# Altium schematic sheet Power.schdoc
size 282 x 196 mm
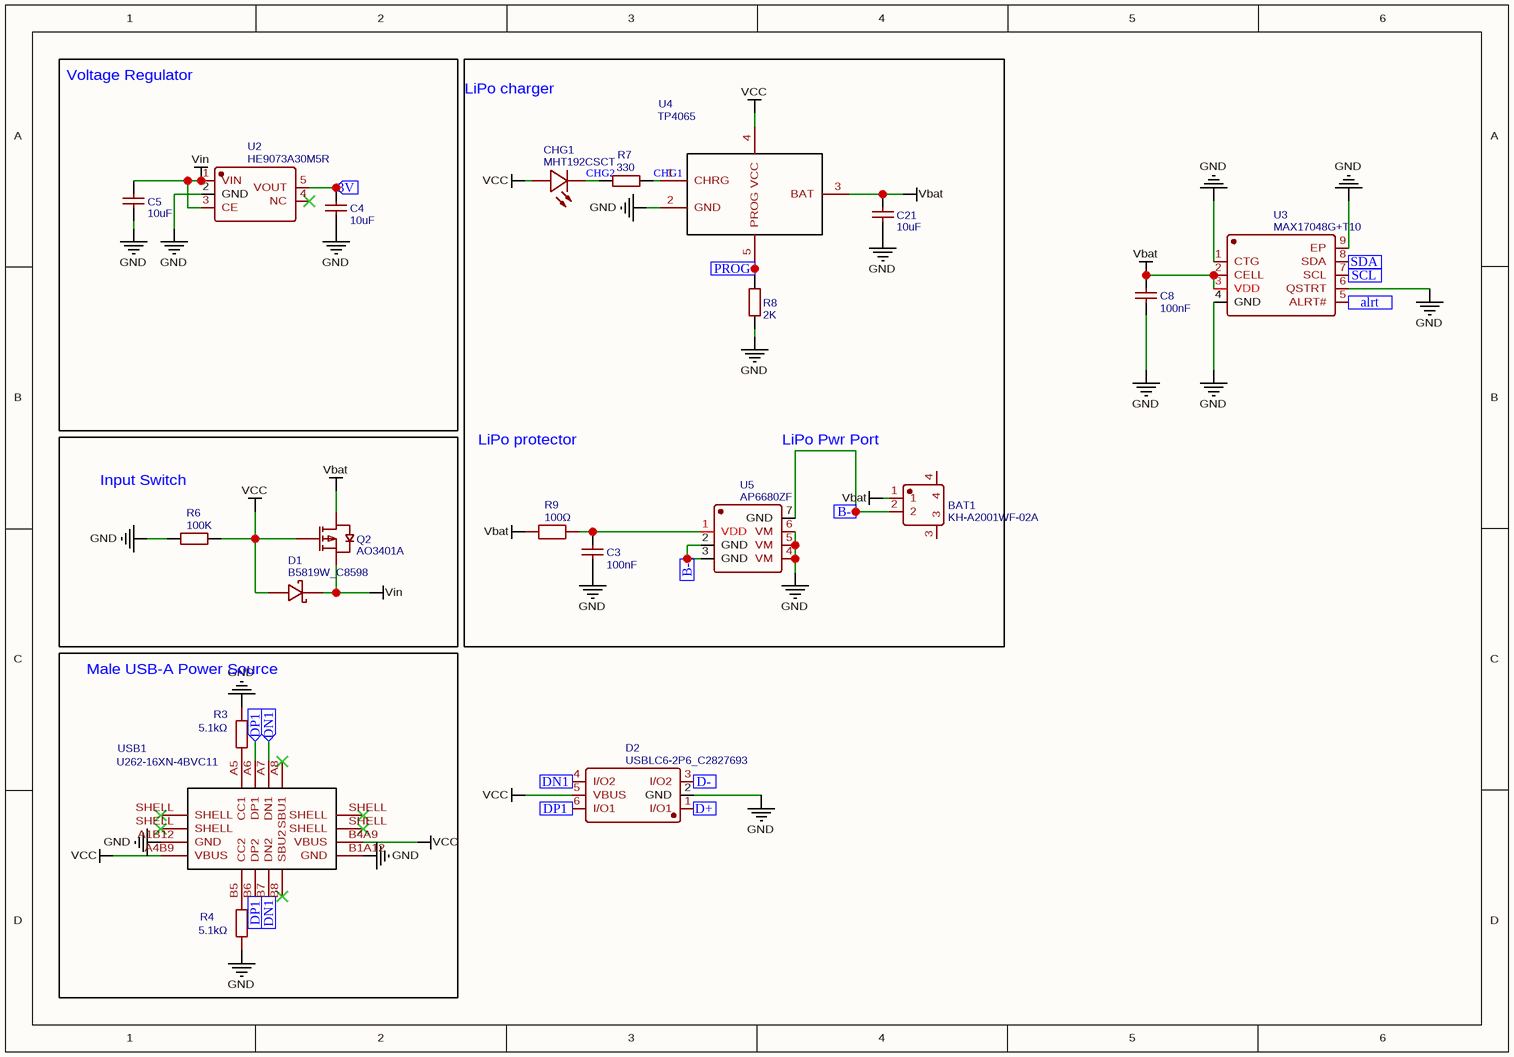
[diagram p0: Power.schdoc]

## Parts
BAT1  KH-A2001WF-02A  [CONN-SMD_KH-A2001WF-02A]
C3  100nF  [C0402]
C4  10uF  [C0402]
C5  10uF  [C0402]
C8  100nF  [C0402]
C21  10uF  [C0402]
CHG1  MHT192CSCT  [LED0603-R-RD_ORANGE]
D1  B5819W_C8598  [SOD-123_L2.7-W1.6-LS3.7-RD-1]
D2  USBLC6-2P6_C2827693  [SOT-666-6_L1.6-W1.2-P0.50-LS1.6-BL]
Q2  AO3401A  [SOT-23_L2.9-W1.3-P0.95-LS2.4-BR]
R3  5.1kΩ  [R0402]
R4  5.1kΩ  [R0402]
R6  100K  [R0402]
R7  330  [R0402]
R8  2K  [R0402]
R9  100Ω  [R0402]
U2  HE9073A30M5R  [SOT-23-5_L3.0-W1.7-P0.95-LS2.8-BL]
U3  MAX17048G+T10  [DFN-8_L2.0-W2.0-P0.50-BL-EP]
U4  TP4065  [SOT-23-5_L3.0-W1.7-P0.95-LS2.8-BR]
U5  AP6680ZF  [DFN-6_L2.0-W2.0-P0.65-BL-EP1.2]
USB1  U262-16XN-4BVC11  [USB-3.1-SMD_U262-161N-4BVC11]

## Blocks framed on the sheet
Voltage Regulator: C4 C5 U2
Input Switch: D1 Q2 R6
Male USB-A Power Source: R3 R4 USB1

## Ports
3V (in), alrt (in), B- (in), D+ (in), D- (in), DN1 (in), DP1 (in), PROG (in), SCL (in), SDA (in)

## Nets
GND: C3.1 C4.1 C5.1 C8.1 C21.1 D2.2(GND) R3.2 R4.1 R6.1 R8.1 U2.2(GND) U3.1(CTG) U3.4(GND) U3.6(QSTRT) U3.9(EP) U4.2(GND) U5.4(VM) U5.5(VM) U5.6(VM) USB1.A1B12(GND) USB1.B1A12(GND)
Vbat: BAT1.1 C8.2 C21.2 Q2.3(D) R9.1 U3.2(CELL) U3.3(VDD) U4.3(BAT)
VCC: CHG1.1(A) D1.2(+) D2.5(VBUS) Q2.1(G) R6.2 U4.4(VCC) USB1.A4B9(VBUS) USB1.B4A9(VBUS)
Vin: C5.2 D1.1(-) Q2.2(S) U2.1(VIN) U2.3(CE)
3V: C4.2 U2.5(VOUT) ; port 3V
alrt: U3.5(ALRT#) ; port alrt
B-: BAT1.2 U5.2(GND) U5.3(GND) U5.7(GND) ; port B-
CHG1: R7.2 U4.1(CHRG)
CHG2: CHG1.2(K) R7.1
D+: D2.1(I/O1) ; port D+
D-: D2.3(I/O2) ; port D-
DN1: D2.4(I/O2) USB1.A7(DN1) USB1.B7(DN2) ; port DN1
DP1: D2.6(I/O1) USB1.A6(DP1) USB1.B6(DP2) ; port DP1
PROG: R8.2 U4.5(PROG) ; port PROG
SCL: U3.7(SCL) ; port SCL
SDA: U3.8(SDA) ; port SDA
NetC3_2: C3.2 R9.2 U5.1(VDD)
NetR3_1: R3.1 USB1.A5(CC1)
NetR4_2: R4.2 USB1.B5(CC2)

Not connected (* = marked no-connect by the designer): BAT1 3 4; U2 4(NC)*; USB1 A8(SBU1)* B8(SBU2)* SHELL*

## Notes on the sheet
- LiPo charger
- LiPo protector
- LiPo Pwr Port

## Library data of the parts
BAT1 = KH-A2001WF-02A: Manufacturer: kinghelm(金航标); Contributor: LCSC
C3 C8 = 100nF: Manufacturer: FH(风华); Manufacturer Part: 0402B104K160NT; nameAlias: Capacitance
C4 C5 C21 = 10uF: Manufacturer Part: CL05A106MQ5NUNC; Manufacturer: SAMSUNG; nameAlias: Capacitance; SMT Type: Basic
CHG1 = MHT192CSCT: Manufacturer: MEIHUA(美华); Contributor: LCSC
D1 = B5819W_C8598: Manufacturer: CJ; Manufacturer Part: B5819W
D2 = USBLC6-2P6_C2827693: Manufacturer: TECH PUBLIC(台舟); Contributor: LCSC
Q2 = AO3401A: Manufacturer: AOS; SMT Type: Basic
R3 R4 = 5.1kΩ: Manufacturer: 大毅科技; Manufacturer Part: RM04FTN5101; Resistance (Ohms): 5.1K; nameAlias: Resistance; Contributor: LCSC
R6 = 100K: Manufacturer: UniOhm; Manufacturer Part: 0402WGF1003TCE; nameAlias: Resistance (Ohms)
R7 = 330: Manufacturer: UniOhm; Manufacturer Part: 0402WGF3300TCE; nameAlias: Resistance (Ohms)
R8 = 2K: Manufacturer Part: 0402WGF2001TCE; Manufacturer: UniOhm; nameAlias: Resistance (Ohms)
R9 = 100Ω: Manufacturer: VO(翔胜); Manufacturer Part: SCR0402J100R; Contributor: lcsc; nameAlias: Value
U2 = HE9073A30M5R: Manufacturer: HEERMICR(赫尔半导体); Contributor: LCSC
U3 = MAX17048G+T10: Manufacturer: ADI(亚德诺); Contributor: LCSC
U4 = TP4065: Manufacturer: TOPPOWER
U5 = AP6680ZF: Manufacturer: ALLPOWER(铨力); Contributor: LCSC
USB1 = U262-16XN-4BVC11: Manufacturer: XKB Connectivity(中国星坤); Manufacturer Part: U262-161N-4BVC11; Contributor: LCSC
